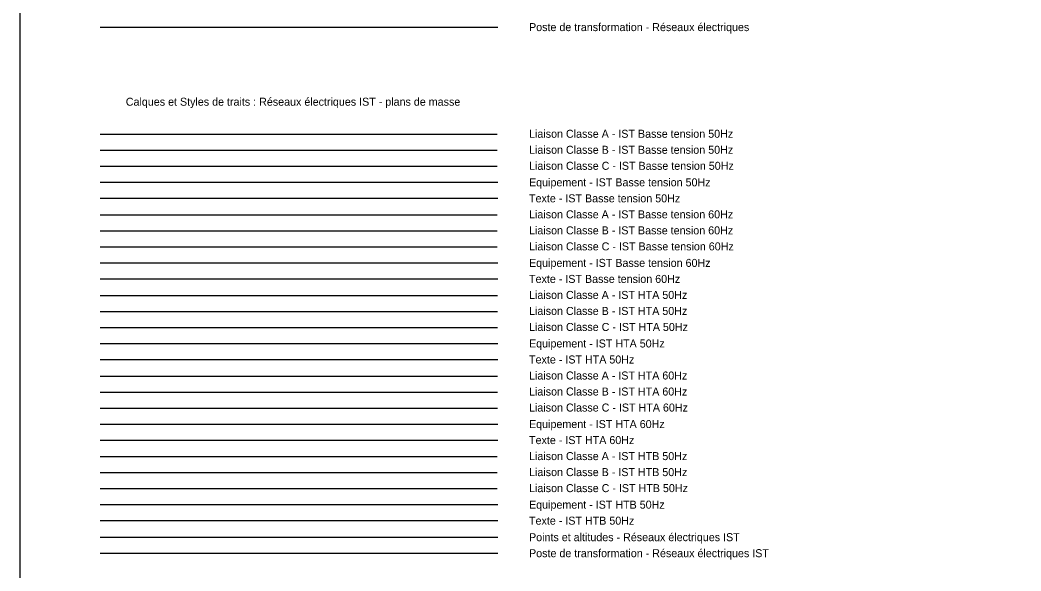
# Model space of a CAD drawing. Extents: x 703432 to 707394, y 7057985 to 7059523.
# Drawn here: x 707199.5 to 707262, y 7058534.5 to 7058568.9 of the extents above; entities that cross this region are included whole.
import ezdxf

# ---------------------------------------------------------------- set-up
doc = ezdxf.new("R2010")
doc.units = 0
for name, color, linetype in [('DH_CADRE -CARTOUCHE', 7, 'Continuous'), ('R_ELEC_IST_ALT_POINT', 7, 'Continuous'), ('R_ELEC_IST_BT_50HZ_EQUIP', 7, 'Continuous'), ('R_ELEC_IST_BT_50HZ_LIAISON_CL_A', 7, 'Continuous'), ('R_ELEC_IST_BT_50HZ_LIAISON_CL_B', 7, 'Continuous'), ('R_ELEC_IST_BT_50HZ_LIAISON_CL_C', 7, 'Continuous'), ('R_ELEC_IST_BT_50HZ_TEXTE', 7, 'Continuous'), ('R_ELEC_IST_BT_60HZ_EQUIP', 7, 'Continuous'), ('R_ELEC_IST_BT_60HZ_LIAISON_CL_A', 7, 'Continuous'), ('R_ELEC_IST_BT_60HZ_LIAISON_CL_B', 7, 'Continuous'), ('R_ELEC_IST_BT_60HZ_LIAISON_CL_C', 7, 'Continuous'), ('R_ELEC_IST_BT_60HZ_TEXTE', 7, 'Continuous'), ('R_ELEC_IST_HTA_50HZ_EQUIP', 7, 'Continuous'), ('R_ELEC_IST_HTA_50HZ_LIAISON_CL_A', 7, 'Continuous'), ('R_ELEC_IST_HTA_50HZ_LIAISON_CL_B', 7, 'Continuous'), ('R_ELEC_IST_HTA_50HZ_LIAISON_CL_C', 7, 'Continuous'), ('R_ELEC_IST_HTA_50HZ_TEXTE', 7, 'Continuous'), ('R_ELEC_IST_HTA_60HZ_EQUIP', 7, 'Continuous'), ('R_ELEC_IST_HTA_60HZ_LIAISON_CL_A', 7, 'Continuous'), ('R_ELEC_IST_HTA_60HZ_LIAISON_CL_B', 7, 'Continuous'), ('R_ELEC_IST_HTA_60HZ_LIAISON_CL_C', 7, 'Continuous'), ('R_ELEC_IST_HTA_60HZ_TEXTE', 7, 'Continuous'), ('R_ELEC_IST_HTB_50HZ_EQUIP', 7, 'Continuous'), ('R_ELEC_IST_HTB_50HZ_LIAISON_CL_A', 7, 'Continuous'), ('R_ELEC_IST_HTB_50HZ_LIAISON_CL_B', 7, 'Continuous'), ('R_ELEC_IST_HTB_50HZ_LIAISON_CL_C', 7, 'Continuous'), ('R_ELEC_IST_HTB_50HZ_TEXTE', 7, 'Continuous'), ('R_ELEC_IST_POSTE', 7, 'Continuous'), ('R_ELEC_POSTE', 7, 'Continuous')]:
    doc.layers.add(name, color=color, linetype=linetype)

msp = doc.modelspace()

# ---------------------------------------------------------------- linework, layer by layer
at = {"layer": 'DH_CADRE -CARTOUCHE'}
msp.add_lwpolyline([(707199.469, 7058644.551), (707324.469, 7058644.551), (707324.469, 7058419.551), (707199.469, 7058419.551)], close=True, dxfattribs=at)
at = {"layer": 'R_ELEC_IST_ALT_POINT'}
msp.add_line((707204.469, 7058536.608), (707229.298, 7058536.608), dxfattribs=at)
at = {"layer": 'R_ELEC_IST_BT_50HZ_EQUIP'}
msp.add_line((707204.469, 7058558.763), (707229.298, 7058558.763), dxfattribs=at)
at = {"layer": 'R_ELEC_IST_BT_50HZ_LIAISON_CL_A'}
msp.add_line((707204.469, 7058561.763), (707229.254, 7058561.763), dxfattribs=at)
at = {"layer": 'R_ELEC_IST_BT_50HZ_LIAISON_CL_B'}
msp.add_line((707204.469, 7058560.763), (707229.254, 7058560.763), dxfattribs=at)
at = {"layer": 'R_ELEC_IST_BT_50HZ_LIAISON_CL_C'}
msp.add_line((707204.469, 7058559.763), (707229.254, 7058559.763), dxfattribs=at)
at = {"layer": 'R_ELEC_IST_BT_50HZ_TEXTE'}
msp.add_line((707204.469, 7058557.763), (707229.298, 7058557.763), dxfattribs=at)
at = {"layer": 'R_ELEC_IST_BT_60HZ_EQUIP'}
msp.add_line((707204.469, 7058553.732), (707229.298, 7058553.732), dxfattribs=at)
at = {"layer": 'R_ELEC_IST_BT_60HZ_LIAISON_CL_A'}
msp.add_line((707204.469, 7058556.732), (707229.269, 7058556.732), dxfattribs=at)
at = {"layer": 'R_ELEC_IST_BT_60HZ_LIAISON_CL_B'}
msp.add_line((707204.469, 7058555.732), (707229.269, 7058555.732), dxfattribs=at)
at = {"layer": 'R_ELEC_IST_BT_60HZ_LIAISON_CL_C'}
msp.add_line((707204.469, 7058554.732), (707229.269, 7058554.732), dxfattribs=at)
at = {"layer": 'R_ELEC_IST_BT_60HZ_TEXTE'}
msp.add_line((707204.469, 7058552.732), (707229.298, 7058552.732), dxfattribs=at)
at = {"layer": 'R_ELEC_IST_HTA_50HZ_EQUIP'}
msp.add_line((707204.469, 7058548.701), (707229.298, 7058548.701), dxfattribs=at)
at = {"layer": 'R_ELEC_IST_HTA_50HZ_LIAISON_CL_A'}
msp.add_line((707204.469, 7058551.701), (707229.284, 7058551.701), dxfattribs=at)
at = {"layer": 'R_ELEC_IST_HTA_50HZ_LIAISON_CL_B'}
msp.add_line((707204.469, 7058550.701), (707229.284, 7058550.701), dxfattribs=at)
at = {"layer": 'R_ELEC_IST_HTA_50HZ_LIAISON_CL_C'}
msp.add_line((707204.469, 7058549.701), (707229.284, 7058549.701), dxfattribs=at)
at = {"layer": 'R_ELEC_IST_HTA_50HZ_TEXTE'}
msp.add_line((707204.469, 7058547.701), (707229.298, 7058547.701), dxfattribs=at)
at = {"layer": 'R_ELEC_IST_HTA_60HZ_EQUIP'}
msp.add_line((707204.469, 7058543.67), (707229.298, 7058543.67), dxfattribs=at)
at = {"layer": 'R_ELEC_IST_HTA_60HZ_LIAISON_CL_A'}
msp.add_line((707204.469, 7058546.67), (707229.284, 7058546.67), dxfattribs=at)
at = {"layer": 'R_ELEC_IST_HTA_60HZ_LIAISON_CL_B'}
msp.add_line((707204.469, 7058545.67), (707229.284, 7058545.67), dxfattribs=at)
at = {"layer": 'R_ELEC_IST_HTA_60HZ_LIAISON_CL_C'}
msp.add_line((707204.469, 7058544.67), (707229.284, 7058544.67), dxfattribs=at)
at = {"layer": 'R_ELEC_IST_HTA_60HZ_TEXTE'}
msp.add_line((707204.469, 7058542.67), (707229.298, 7058542.67), dxfattribs=at)
at = {"layer": 'R_ELEC_IST_HTB_50HZ_EQUIP'}
msp.add_line((707204.469, 7058538.639), (707229.298, 7058538.639), dxfattribs=at)
at = {"layer": 'R_ELEC_IST_HTB_50HZ_LIAISON_CL_A'}
msp.add_line((707204.469, 7058541.639), (707229.254, 7058541.639), dxfattribs=at)
at = {"layer": 'R_ELEC_IST_HTB_50HZ_LIAISON_CL_B'}
msp.add_line((707204.469, 7058540.639), (707229.254, 7058540.639), dxfattribs=at)
at = {"layer": 'R_ELEC_IST_HTB_50HZ_LIAISON_CL_C'}
msp.add_line((707204.469, 7058539.639), (707229.254, 7058539.639), dxfattribs=at)
at = {"layer": 'R_ELEC_IST_HTB_50HZ_TEXTE'}
msp.add_line((707204.469, 7058537.639), (707229.298, 7058537.639), dxfattribs=at)
at = {"layer": 'R_ELEC_IST_POSTE'}
msp.add_line((707204.469, 7058535.608), (707229.298, 7058535.608), dxfattribs=at)
at = {"layer": 'R_ELEC_POSTE'}
msp.add_line((707204.469, 7058568.453), (707229.298, 7058568.453), dxfattribs=at)

# ---------------------------------------------------------------- texts
at = {"layer": 'DH_CADRE -CARTOUCHE'}
msp.add_text(' Calques et Styles de traits : Réseaux électriques IST - plans de masse', height=0.5, dxfattribs=at).set_placement((707205.888, 7058563.544))
at = {"layer": 'R_ELEC_IST_ALT_POINT'}
msp.add_text('Points et altitudes - Réseaux électriques IST', height=0.5, dxfattribs=at).set_placement((707231.252, 7058536.358))
at = {"layer": 'R_ELEC_IST_BT_50HZ_EQUIP'}
msp.add_text('Equipement - IST Basse tension 50Hz', height=0.5, dxfattribs=at).set_placement((707231.252, 7058558.513))
at = {"layer": 'R_ELEC_IST_BT_50HZ_LIAISON_CL_A'}
msp.add_text('Liaison Classe A - IST Basse tension 50Hz', height=0.5, dxfattribs=at).set_placement((707231.252, 7058561.544))
at = {"layer": 'R_ELEC_IST_BT_50HZ_LIAISON_CL_B'}
msp.add_text('Liaison Classe B - IST Basse tension 50Hz', height=0.5, dxfattribs=at).set_placement((707231.252, 7058560.544))
at = {"layer": 'R_ELEC_IST_BT_50HZ_LIAISON_CL_C'}
msp.add_text('Liaison Classe C - IST Basse tension 50Hz', height=0.5, dxfattribs=at).set_placement((707231.252, 7058559.544))
at = {"layer": 'R_ELEC_IST_BT_50HZ_TEXTE'}
msp.add_text('Texte - IST Basse tension 50Hz', height=0.5, dxfattribs=at).set_placement((707231.252, 7058557.513))
at = {"layer": 'R_ELEC_IST_BT_60HZ_EQUIP'}
msp.add_text('Equipement - IST Basse tension 60Hz', height=0.5, dxfattribs=at).set_placement((707231.252, 7058553.482))
at = {"layer": 'R_ELEC_IST_BT_60HZ_LIAISON_CL_A'}
msp.add_text('Liaison Classe A - IST Basse tension 60Hz', height=0.5, dxfattribs=at).set_placement((707231.252, 7058556.513))
at = {"layer": 'R_ELEC_IST_BT_60HZ_LIAISON_CL_B'}
msp.add_text('Liaison Classe B - IST Basse tension 60Hz', height=0.5, dxfattribs=at).set_placement((707231.252, 7058555.513))
at = {"layer": 'R_ELEC_IST_BT_60HZ_LIAISON_CL_C'}
msp.add_text('Liaison Classe C - IST Basse tension 60Hz', height=0.5, dxfattribs=at).set_placement((707231.252, 7058554.513))
at = {"layer": 'R_ELEC_IST_BT_60HZ_TEXTE'}
msp.add_text('Texte - IST Basse tension 60Hz', height=0.5, dxfattribs=at).set_placement((707231.252, 7058552.482))
at = {"layer": 'R_ELEC_IST_HTA_50HZ_EQUIP'}
msp.add_text('Equipement - IST HTA 50Hz', height=0.5, dxfattribs=at).set_placement((707231.252, 7058548.451))
at = {"layer": 'R_ELEC_IST_HTA_50HZ_LIAISON_CL_A'}
msp.add_text('Liaison Classe A - IST HTA 50Hz', height=0.5, dxfattribs=at).set_placement((707231.252, 7058551.482))
at = {"layer": 'R_ELEC_IST_HTA_50HZ_LIAISON_CL_B'}
msp.add_text('Liaison Classe B - IST HTA 50Hz', height=0.5, dxfattribs=at).set_placement((707231.252, 7058550.482))
at = {"layer": 'R_ELEC_IST_HTA_50HZ_LIAISON_CL_C'}
msp.add_text('Liaison Classe C - IST HTA 50Hz', height=0.5, dxfattribs=at).set_placement((707231.252, 7058549.482))
at = {"layer": 'R_ELEC_IST_HTA_50HZ_TEXTE'}
msp.add_text('Texte - IST HTA 50Hz', height=0.5, dxfattribs=at).set_placement((707231.252, 7058547.451))
at = {"layer": 'R_ELEC_IST_HTA_60HZ_EQUIP'}
msp.add_text('Equipement - IST HTA 60Hz', height=0.5, dxfattribs=at).set_placement((707231.252, 7058543.42))
at = {"layer": 'R_ELEC_IST_HTA_60HZ_LIAISON_CL_A'}
msp.add_text('Liaison Classe A - IST HTA 60Hz', height=0.5, dxfattribs=at).set_placement((707231.252, 7058546.451))
at = {"layer": 'R_ELEC_IST_HTA_60HZ_LIAISON_CL_B'}
msp.add_text('Liaison Classe B - IST HTA 60Hz', height=0.5, dxfattribs=at).set_placement((707231.252, 7058545.451))
at = {"layer": 'R_ELEC_IST_HTA_60HZ_LIAISON_CL_C'}
msp.add_text('Liaison Classe C - IST HTA 60Hz', height=0.5, dxfattribs=at).set_placement((707231.252, 7058544.451))
at = {"layer": 'R_ELEC_IST_HTA_60HZ_TEXTE'}
msp.add_text('Texte - IST HTA 60Hz', height=0.5, dxfattribs=at).set_placement((707231.252, 7058542.42))
at = {"layer": 'R_ELEC_IST_HTB_50HZ_EQUIP'}
msp.add_text('Equipement - IST HTB 50Hz', height=0.5, dxfattribs=at).set_placement((707231.252, 7058538.389))
at = {"layer": 'R_ELEC_IST_HTB_50HZ_LIAISON_CL_A'}
msp.add_text('Liaison Classe A - IST HTB 50Hz', height=0.5, dxfattribs=at).set_placement((707231.252, 7058541.42))
at = {"layer": 'R_ELEC_IST_HTB_50HZ_LIAISON_CL_B'}
msp.add_text('Liaison Classe B - IST HTB 50Hz', height=0.5, dxfattribs=at).set_placement((707231.252, 7058540.42))
at = {"layer": 'R_ELEC_IST_HTB_50HZ_LIAISON_CL_C'}
msp.add_text('Liaison Classe C - IST HTB 50Hz', height=0.5, dxfattribs=at).set_placement((707231.252, 7058539.42))
at = {"layer": 'R_ELEC_IST_HTB_50HZ_TEXTE'}
msp.add_text('Texte - IST HTB 50Hz', height=0.5, dxfattribs=at).set_placement((707231.252, 7058537.389))
at = {"layer": 'R_ELEC_IST_POSTE'}
msp.add_text('Poste de transformation - Réseaux électriques IST', height=0.5, dxfattribs=at).set_placement((707231.252, 7058535.358))
at = {"layer": 'R_ELEC_POSTE'}
msp.add_text('Poste de transformation - Réseaux électriques', height=0.5, dxfattribs=at).set_placement((707231.252, 7058568.203))

doc.saveas('drawing.dxf')
